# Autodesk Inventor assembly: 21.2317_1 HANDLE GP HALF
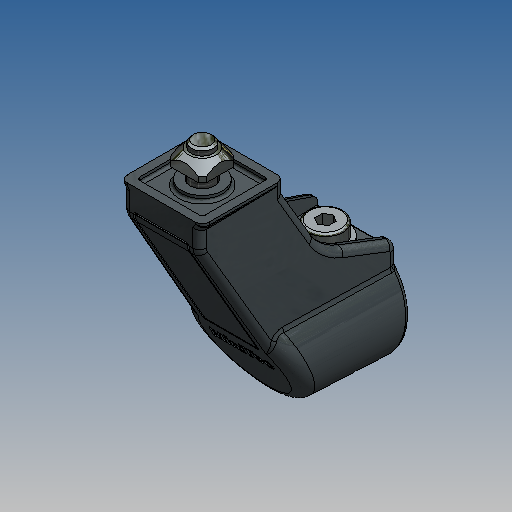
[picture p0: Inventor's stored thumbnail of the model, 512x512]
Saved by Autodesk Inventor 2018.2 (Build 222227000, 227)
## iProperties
Created: 2019-10
Part Number: 21.2317_1 HANDLE GP HALF
Description: Handgriff GP Bausatz ohne Profil
Document SubType Name: Assembly
Designer: amoles
Mass: 80.6784 g
Surface Area: 266.153 cm^2
Volume: 46.6325 cm^3
Density: 1.73009 g/cm^3
Sending System: Autodesk Inventor 2019
Preprocessor: ST-DEVELOPER v17.2
Title: C:\Users\metz\Desktop\212\212317-1.stp
Author: Metz
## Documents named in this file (8)
- Y:\INVENTOR LIBRARIES\PARTS LIBRARY\HANDLES LOCKS STOPS\21.2317_1 HANDLE GP HALF.iam
- Y:\INVENTOR LIBRARIES\PARTS LIBRARY\HANDLES LOCKS STOPS\SUBCOMPONENTS\21.2317_1 Handle GP Plastic Base.ipt
- Y:\INVENTOR LIBRARIES\PARTS LIBRARY\HANDLES LOCKS STOPS\SUBCOMPONENTS\21.2317_1 Handle GP CAP.ipt
- Y:\INVENTOR LIBRARIES\PARTS LIBRARY\FASTENING ELEMENTS\WASHERS\21.1127 M8 ROUND WASHER.ipt
- Y:\INVENTOR LIBRARIES\PARTS LIBRARY\FASTENING ELEMENTS\SCREWS CAP\21.1268 M8X18.ipt
- 21.1268 M8X18.ipt
- Y:\INVENTOR LIBRARIES\PARTS LIBRARY\FASTENING ELEMENTS\SCREWS CAP\21.1280 M8X22.ipt
- Y:\INVENTOR LIBRARIES\PARTS LIBRARY\FASTENING ELEMENTS\NUTS\21.1351 M8 SQUARE NUT.ipt
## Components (8 placed, 6 different names)
1. 21.2317_1 Handle GP Plastic Base:1 — Mate:1, Mate:2, Mate:3, Insert:1, Insert:2, Angle:1, Mate:5, Mate:7, Angle:2, Flush:1, Flush:2, Flush:3
2. 21.2317_1 Handle GP CAP:1 — Mate:1, Mate:2, Mate:3
3. 21.1127 WASHER M8:1 — Insert:1, Insert:4
4. 21.1127 WASHER M8:2 — Insert:2, Insert:3
5. 21.1268 M8X18:1 — Insert:3, Mate:4
6. 21.1280 M8X22:1 — Insert:4, Mate:6
7. 21.1351 M8 SQUARE NUT:1 — Mate:4, Angle:1, Mate:5
8. 21.1351 M8 SQUARE NUT:2 — Mate:6, Mate:7, Angle:2
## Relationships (16: Mate 7, Insert 4, Flush 3, Angle 2)
- Mate:1: 21.2317_1 Handle GP Plastic Base:1 ↔ 21.2317_1 Handle GP CAP:1
- Mate:2: 21.2317_1 Handle GP Plastic Base:1 ↔ 21.2317_1 Handle GP CAP:1
- Mate:3: 21.2317_1 Handle GP Plastic Base:1 ↔ 21.2317_1 Handle GP CAP:1
- Insert:1: 21.2317_1 Handle GP Plastic Base:1 ↔ 21.1127 WASHER M8:1
- Insert:2: 21.2317_1 Handle GP Plastic Base:1 ↔ 21.1127 WASHER M8:2
- Insert:3: 21.1127 WASHER M8:2 ↔ 21.1268 M8X18:1
- Insert:4: 21.1127 WASHER M8:1 ↔ 21.1280 M8X22:1
- Mate:4: 21.1268 M8X18:1 ↔ 21.1351 M8 SQUARE NUT:1
- Angle:1: 21.2317_1 Handle GP Plastic Base:1 ↔ 21.1351 M8 SQUARE NUT:1
- Mate:5: 21.2317_1 Handle GP Plastic Base:1 ↔ 21.1351 M8 SQUARE NUT:1
- Mate:6: 21.1280 M8X22:1 ↔ 21.1351 M8 SQUARE NUT:2
- Mate:7: 21.2317_1 Handle GP Plastic Base:1 ↔ 21.1351 M8 SQUARE NUT:2
- Angle:2: 21.2317_1 Handle GP Plastic Base:1 ↔ 21.1351 M8 SQUARE NUT:2
- Flush:1: 21.2317_1 Handle GP Plastic Base:1
- Flush:2: 21.2317_1 Handle GP Plastic Base:1
- Flush:3: 21.2317_1 Handle GP Plastic Base:1
